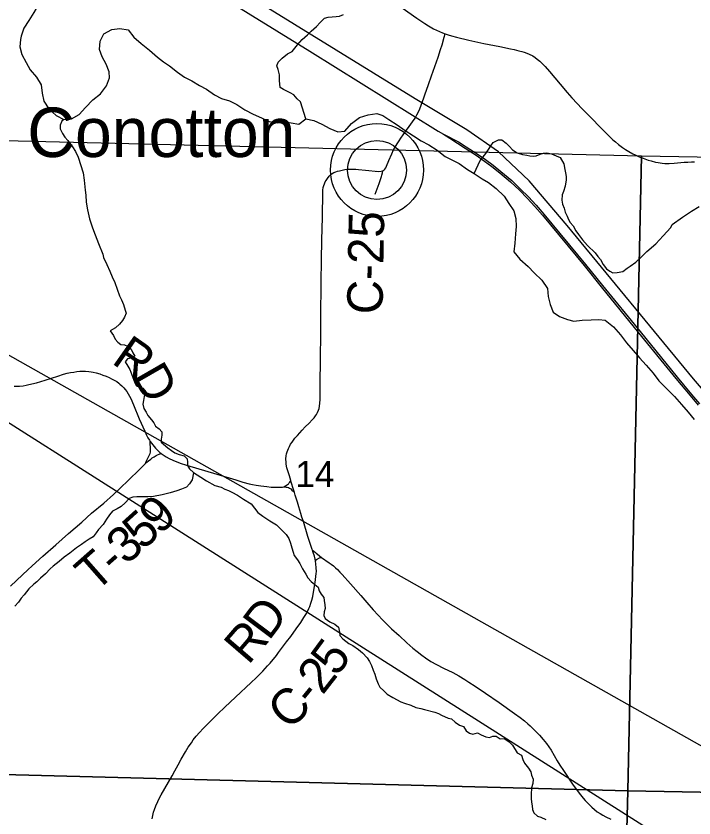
# Model space of a CAD drawing. Extents: x 0 to 34, y 0 to 22.
# Drawn here: x 6.594 to 7.678, y 15.844 to 17.126 of the extents above; entities that cross this region are included whole.
import ezdxf

# ---------------------------------------------------------------- set-up
doc = ezdxf.new("R2010")
doc.units = 0
for name, color, linetype in [('GM_X_Corporation', 7, 'Continuous'), ('GM_X_Corporation_Text', 7, 'Continuous'), ('GM_X_County_Road', 7, 'Continuous'), ('GM_X_County_Road_Text', 7, 'Continuous'), ('GM_X_Interchange_Ramps', 7, 'Continuous'), ('GM_X_Interstate_Route', 7, 'Continuous'), ('GM_X_Major_Lake', 7, 'Continuous'), ('GM_X_Minor_Lake', 7, 'Continuous'), ('GM_X_Section', 7, 'Continuous'), ('GM_X_State_Location', 7, 'Continuous'), ('GM_X_State_Shield', 7, 'Continuous'), ('GM_X_Township_Road_Text', 7, 'Continuous'), ('GM_X_US_Location', 7, 'Continuous'), ('SH_Data', 7, 'Continuous')]:
    doc.layers.add(name, color=color, linetype=linetype)

msp = doc.modelspace()

# ---------------------------------------------------------------- linework, layer by layer
at = {"layer": 'GM_X_Corporation'}
for points in [[(7.2464, 16.9956), (7.2481, 17.0004), (7.2538, 17.0168), (7.2587, 17.0308), (7.2691, 17.0608), (7.2732, 17.073), (7.2756, 17.0805), (7.2789, 17.0927), (7.2803, 17.098)], [(7.0396, 16.3644), (7.038, 16.3695), (7.0345, 16.381), (7.0337, 16.3836), (7.0314, 16.391), (7.0291, 16.3991), (7.0276, 16.4041), (7.0269, 16.4068), (7.0263, 16.4101), (7.0262, 16.4125), (7.0259, 16.4183), (7.0264, 16.4234), (7.027, 16.4266), (7.028, 16.4298), (7.0299, 16.4347), (7.0315, 16.4381), (7.0334, 16.4416), (7.0357, 16.4452), (7.0401, 16.4512), (7.0443, 16.4558), (7.0517, 16.4643), (7.0569, 16.4695), (7.0631, 16.4756), (7.0678, 16.4806), (7.0708, 16.4838), (7.0732, 16.4871), (7.0749, 16.4895), (7.0766, 16.4924), (7.0781, 16.4961), (7.0788, 16.4986), (7.0797, 16.5027), (7.0803, 16.5073), (7.0805, 16.513), (7.0806, 16.5198), (7.0808, 16.5498), (7.081, 16.5657), (7.0811, 16.5722), (7.0812, 16.5824), (7.0813, 16.593), (7.0815, 16.6041), (7.0815, 16.6277), (7.0817, 16.6358), (7.0818, 16.6478), (7.0819, 16.6664), (7.082, 16.6789), (7.0824, 16.6992), (7.0825, 16.7089), (7.0827, 16.7278), (7.0829, 16.7393), (7.0832, 16.7656), (7.0839, 16.7892), (7.0842, 16.8016), (7.0844, 16.8175), (7.0847, 16.8318), (7.0851, 16.8477), (7.0856, 16.8521), (7.0866, 16.8553), (7.0876, 16.8583), (7.0888, 16.8611), (7.0902, 16.8636), (7.0923, 16.8666), (7.0953, 16.8702), (7.0973, 16.8723), (7.0997, 16.8744), (7.1026, 16.8761), (7.1055, 16.8774), (7.1086, 16.8783), (7.1117, 16.8791), (7.1158, 16.8802), (7.1201, 16.8809), (7.1252, 16.8815), (7.1376, 16.8813), (7.1422, 16.8811), (7.1532, 16.8802), (7.1741, 16.878), (7.1782, 16.8781), (7.1806, 16.8788), (7.1816, 16.8794), (7.1828, 16.8803), (7.1841, 16.8817), (7.1856, 16.8839), (7.1869, 16.8866), (7.1904, 16.8953), (7.1951, 16.9062), (7.1981, 16.9125), (7.2004, 16.9167), (7.2038, 16.9223), (7.2068, 16.9268), (7.2097, 16.9313), (7.217, 16.9417), (7.2227, 16.9498), (7.2282, 16.9573), (7.2323, 16.9632), (7.2354, 16.9684), (7.2379, 16.9731), (7.2399, 16.9779), (7.2443, 16.9899), (7.2464, 16.9956)], [(6.5914, 16.5343), (6.5957, 16.5345), (6.6002, 16.5348), (6.6057, 16.5353), (6.6104, 16.5362), (6.6151, 16.5373), (6.6269, 16.5401), (6.641, 16.5441), (6.6614, 16.5508), (6.6701, 16.5535), (6.6763, 16.5551), (6.6817, 16.5564), (6.687, 16.5572), (6.6915, 16.5579), (6.6963, 16.5583), (6.7008, 16.5586), (6.7053, 16.5584), (6.7106, 16.558), (6.7143, 16.5574), (6.718, 16.5569), (6.7228, 16.5557), (6.7282, 16.5541), (6.7334, 16.5522), (6.7386, 16.5503), (6.7432, 16.5483), (6.7471, 16.5463), (6.7515, 16.5442), (6.7556, 16.5418), (6.7586, 16.5396), (6.7606, 16.5379), (6.7638, 16.535), (6.7666, 16.5321), (6.7691, 16.5291), (6.7715, 16.5258), (6.7735, 16.5225), (6.7777, 16.5146), (6.7823, 16.5047), (6.7915, 16.4824), (6.8001, 16.4624), (6.8028, 16.4564), (6.805, 16.4522), (6.8076, 16.4481), (6.809, 16.4461), (6.8109, 16.4435), (6.815, 16.4383), (6.8174, 16.4354), (6.8211, 16.4316), (6.8245, 16.4286), (6.8266, 16.4269), (6.8279, 16.426), (6.8296, 16.4248), (6.8347, 16.4218), (6.8395, 16.4189), (6.8453, 16.4163), (6.8517, 16.4136), (6.8586, 16.4111), (6.8725, 16.4067), (6.9102, 16.3955), (6.9456, 16.3847), (6.9572, 16.3812), (6.9674, 16.3785), (6.9725, 16.3773), (6.9786, 16.3762), (6.986, 16.375), (6.9952, 16.3739), (7.0024, 16.3733), (7.0096, 16.3731), (7.0157, 16.3732), (7.0204, 16.3733), (7.0228, 16.3734)], [(7.0228, 16.3734), (7.0252, 16.375), (7.0269, 16.3762), (7.0285, 16.3774), (7.0299, 16.3786), (7.0306, 16.3794), (7.0319, 16.381), (7.0331, 16.3827), (7.0337, 16.3836)], [(7.0228, 16.3734), (7.0265, 16.3732), (7.0279, 16.373), (7.0301, 16.3723), (7.0318, 16.3715), (7.0337, 16.3702), (7.0356, 16.3685), (7.0375, 16.3665), (7.0396, 16.3644)], [(7.0683, 16.2724), (7.0678, 16.2736), (7.0662, 16.2783), (7.0611, 16.2942), (7.0539, 16.3179), (7.0516, 16.3251), (7.0497, 16.3312), (7.0466, 16.3417), (7.0444, 16.349), (7.0408, 16.3604), (7.0396, 16.3644)], [(6.812, 15.8428), (6.8131, 15.8481), (6.8144, 15.8532), (6.8159, 15.8579), (6.818, 15.8637), (6.8209, 15.8705), (6.8239, 15.8764), (6.8264, 15.881), (6.8438, 15.9117), (6.8484, 15.9197), (6.8537, 15.9288), (6.8586, 15.9381), (6.8652, 15.9497), (6.8697, 15.9572), (6.8747, 15.9643), (6.8777, 15.969), (6.8826, 15.9748), (6.8876, 15.9807), (6.8936, 15.9871), (6.9011, 15.9947), (6.91, 16.0036), (6.9172, 16.0108), (6.9282, 16.0214), (6.9451, 16.037), (6.9701, 16.0608), (6.9781, 16.0682), (6.9888, 16.079), (6.9965, 16.0872), (7.0006, 16.0918), (7.0109, 16.1041), (7.0143, 16.1086), (7.0269, 16.1255), (7.0335, 16.1343), (7.0422, 16.1463), (7.0495, 16.1568), (7.0546, 16.1644), (7.0586, 16.1709), (7.0603, 16.174), (7.0628, 16.179), (7.0642, 16.1824), (7.0659, 16.1874), (7.0674, 16.1926), (7.0687, 16.1983), (7.0713, 16.2118), (7.0727, 16.2208), (7.0745, 16.2352), (7.0747, 16.238), (7.0745, 16.2441), (7.0739, 16.2506), (7.0733, 16.2547), (7.0726, 16.258), (7.0714, 16.2629), (7.0695, 16.2688), (7.0683, 16.2724)], [(7.0683, 16.2724), (7.0699, 16.2711), (7.0711, 16.2701), (7.0724, 16.269), (7.074, 16.2676), (7.0764, 16.2657), (7.0795, 16.2631), (7.083, 16.2606), (7.0953, 16.252), (7.0982, 16.25), (7.1019, 16.2471), (7.1053, 16.2442), (7.1084, 16.2412), (7.1121, 16.2373), (7.1159, 16.2332), (7.129, 16.2184), (7.1457, 16.1996), (7.1554, 16.1886), (7.1656, 16.177), (7.1732, 16.1685), (7.1804, 16.1608), (7.1891, 16.1522), (7.1949, 16.1467), (7.2067, 16.1357), (7.2193, 16.1242), (7.2288, 16.1158), (7.2355, 16.1102), (7.2431, 16.1043), (7.249, 16.1002), (7.2578, 16.0945), (7.2665, 16.0897), (7.278, 16.0839), (7.2926, 16.0768), (7.3023, 16.0715), (7.3118, 16.0657), (7.3186, 16.0614), (7.3283, 16.0551), (7.3451, 16.0435), (7.3668, 16.0285), (7.3915, 16.011), (7.4002, 16.0048), (7.4072, 15.9994), (7.4126, 15.9948), (7.4163, 15.9914), (7.4203, 15.9878), (7.4261, 15.982), (7.4314, 15.9765), (7.4371, 15.9697), (7.4423, 15.9633), (7.4462, 15.9576), (7.4497, 15.9523), (7.4546, 15.9441), (7.4594, 15.9352), (7.4638, 15.9284), (7.4695, 15.9199), (7.4843, 15.8981), (7.4917, 15.8878), (7.4967, 15.8812), (7.501, 15.8759), (7.5044, 15.8721), (7.5101, 15.8664), (7.515, 15.8615), (7.5194, 15.8576), (7.5237, 15.8541), (7.5281, 15.8511), (7.5323, 15.8484), (7.5371, 15.8459), (7.5453, 15.8422)], [(7.0733, 16.2547), (7.0743, 16.2562), (7.075, 16.2572), (7.0759, 16.258), (7.0768, 16.2587), (7.0777, 16.2592), (7.0786, 16.2596), (7.0798, 16.2599), (7.083, 16.2606)]]:
    msp.add_lwpolyline(points, dxfattribs=at)
at = {"layer": 'GM_X_County_Road'}
for points in [[(8.9, 16.3458), (8.8896, 16.3484), (8.8415, 16.3566), (8.7835, 16.3626), (8.6949, 16.3631), (8.0785, 16.3449), (8.0171, 16.3505), (7.9686, 16.3596), (7.9232, 16.3737), (7.8664, 16.3974), (7.8219, 16.4192), (7.7822, 16.4429), (7.7542, 16.4676), (7.7187, 16.4982), (7.6774, 16.5465), (7.4755, 16.7917), (7.4147, 16.863), (7.366, 16.9092), (7.315, 16.9447), (7.2325, 16.9942), (7.0394, 17.1127), (6.8369, 17.2379), (6.5407, 17.4237)], [(6.5677, 17.3781), (6.8144, 17.2247), (7.064, 17.07), (7.2695, 16.9425), (7.2777, 16.9375), (7.3019, 16.9255), (7.3143, 16.9173), (7.3316, 16.9061), (7.3452, 16.8969), (7.357, 16.888), (7.3696, 16.8779), (7.387, 16.8636), (7.4011, 16.8497), (7.4139, 16.8372), (7.4259, 16.8238), (7.4384, 16.8097), (7.5048, 16.7293), (7.5321, 16.6954), (7.592, 16.6219), (7.6516, 16.5487), (7.6743, 16.5214), (7.6872, 16.5062)], [(7.2777, 16.9375), (7.2882, 16.9311), (7.3127, 16.915), (7.3301, 16.9038), (7.3436, 16.8946), (7.3552, 16.8858), (7.3678, 16.8757), (7.3851, 16.8615), (7.3991, 16.8477), (7.4118, 16.8353), (7.4238, 16.8219), (7.4362, 16.8078), (7.5026, 16.7275), (7.5299, 16.6936), (7.5898, 16.6201), (7.6494, 16.5469), (7.6721, 16.5196), (7.6851, 16.5044)]]:
    msp.add_lwpolyline(points, dxfattribs=at)
at = {"layer": 'GM_X_Interchange_Ramps'}
msp.add_lwpolyline([(7.2116, 17.1397), (7.2354, 17.1231), (7.2479, 17.1146), (7.2536, 17.1109), (7.2621, 17.106), (7.2667, 17.1037), (7.2713, 17.1016), (7.2761, 17.0996), (7.2803, 17.098), (7.2853, 17.0963), (7.2904, 17.0947), (7.2987, 17.0926), (7.3186, 17.0879), (7.3422, 17.0825), (7.3679, 17.0775), (7.3849, 17.0741), (7.391, 17.0727), (7.3985, 17.071), (7.4029, 17.0698), (7.4067, 17.0686), (7.4109, 17.067), (7.4147, 17.0654), (7.4204, 17.0625), (7.4246, 17.0599), (7.4274, 17.0577), (7.4318, 17.0545), (7.4362, 17.0501), (7.4403, 17.0457), (7.4473, 17.0377), (7.4643, 17.0174), (7.4756, 17.0039), (7.4829, 16.9958), (7.4994, 16.9782), (7.508, 16.9693), (7.5346, 16.9424), (7.5413, 16.9357), (7.5488, 16.9286), (7.5527, 16.9252), (7.5578, 16.921), (7.5638, 16.9164), (7.5689, 16.913), (7.5742, 16.9097), (7.5804, 16.9062), (7.5843, 16.9043), (7.5905, 16.9015), (7.5968, 16.899), (7.6051, 16.8961), (7.61, 16.8947), (7.6167, 16.893), (7.621, 16.892), (7.6273, 16.8911), (7.6315, 16.8908), (7.6388, 16.8907), (7.6468, 16.8911), (7.6626, 16.8925), (7.6685, 16.8929), (7.6744, 16.8931), (7.6789, 16.8932)], dxfattribs=at)
at = {"layer": 'GM_X_Interstate_Route'}
for points in [[(7.1764, 16.8633), (7.1786, 16.8696), (7.1792, 16.8717), (7.1801, 16.8756), (7.1806, 16.8788)], [(7.1686, 16.8414), (7.1748, 16.8588), (7.1764, 16.8633)], [(6.8009, 16.4101), (6.8018, 16.4125), (6.8035, 16.416), (6.8053, 16.4194), (6.8069, 16.4226), (6.8078, 16.4247), (6.8087, 16.4271), (6.8092, 16.429), (6.8094, 16.4318), (6.8092, 16.4376), (6.809, 16.4411), (6.809, 16.4461)], [(6.5855, 16.2146), (6.5953, 16.224), (6.6045, 16.2327), (6.6134, 16.2411), (6.62, 16.2471), (6.6374, 16.2628), (6.6579, 16.2808), (6.6785, 16.2988), (6.6997, 16.3173), (6.7153, 16.3313), (6.7346, 16.3475), (6.7502, 16.3614), (6.7598, 16.3704), (6.7907, 16.4), (6.8009, 16.4101), (6.8037, 16.4129), (6.806, 16.4149), (6.8097, 16.4178), (6.8122, 16.4198), (6.815, 16.4217), (6.8182, 16.4236), (6.8204, 16.4247), (6.8234, 16.4259), (6.8266, 16.4269)]]:
    msp.add_lwpolyline(points, dxfattribs=at)
at = {"layer": 'GM_X_Minor_Lake'}
for points in [[(7.5942, 16.9027), (7.5725, 15.8874), (6.553, 15.9139), (6.5754, 16.9273)], [(7.5942, 16.9027), (8.606, 16.8847), (8.5869, 15.8686), (7.5725, 15.8874)], [(7.5725, 15.8874), (7.5466, 14.8803), (6.5307, 14.8925), (6.553, 15.9139)], [(7.5725, 15.8874), (8.5869, 15.8686), (8.5685, 14.859), (7.5466, 14.8803)]]:
    msp.add_lwpolyline(points, close=True, dxfattribs=at)
at = {"layer": 'GM_X_State_Location'}
msp.add_line((7.1715, 16.8802), (7.1715, 16.8802), dxfattribs=at)
at = {"layer": 'GM_X_State_Shield'}
for radius in [0.0744, 0.0472]:
    msp.add_circle((7.1715, 16.8802), radius, dxfattribs=at)
at = {"layer": 'GM_X_Township_Road_Text'}
for points in [[(7.0575, 16.9622), (7.049, 16.9893), (7.044, 16.9942), (7.0383, 17.0006), (7.0325, 17.0035), (7.0276, 17.0065), (7.0219, 17.0091), (7.0169, 17.0121), (7.0156, 17.0231), (7.0155, 17.0326), (7.0134, 17.0409), (7.0115, 17.047), (7.0133, 17.0524), (7.02, 17.0589), (7.0286, 17.0659), (7.0357, 17.0698), (7.0443, 17.0802), (7.0521, 17.0887), (7.0604, 17.0965), (7.0663, 17.1023), (7.0749, 17.1096), (7.0805, 17.1162), (7.0876, 17.1228), (7.0933, 17.1244), (7.1001, 17.1249), (7.1065, 17.1257), (7.1118, 17.1262), (7.1182, 17.1286)], [(6.6706, 16.9609), (6.6675, 16.9584), (6.6649, 16.9519), (6.665, 16.9458), (6.6685, 16.9386), (6.6727, 16.9326), (6.677, 16.9273), (6.6847, 16.9172), (6.6897, 16.9096), (6.6937, 16.9005), (6.7016, 16.8755), (6.7033, 16.8638), (6.7046, 16.8531), (6.705, 16.8482), (6.7059, 16.8402), (6.7068, 16.8288), (6.7089, 16.8166), (6.7121, 16.8022), (6.7165, 16.7878), (6.7208, 16.7765), (6.7263, 16.7628), (6.7334, 16.7454), (6.7342, 16.7401), (6.7397, 16.7292), (6.7444, 16.7182), (6.7483, 16.7095), (6.7522, 16.7004), (6.7561, 16.6894), (6.7597, 16.6788), (6.7628, 16.6724), (6.766, 16.6652), (6.7691, 16.6561), (6.7703, 16.6512), (6.7678, 16.6447), (6.7648, 16.6397), (6.7596, 16.6335), (6.7536, 16.6277), (6.745, 16.623), (6.75, 16.6155), (6.7531, 16.6098), (6.757, 16.6049), (6.762, 16.6012), (6.7677, 16.6005), (6.7726, 16.5983), (6.7787, 16.5935), (6.7811, 16.5878), (6.7846, 16.5825), (6.7793, 16.5794), (6.7725, 16.5785), (6.7688, 16.5735), (6.7731, 16.5663), (6.7765, 16.5614), (6.7797, 16.5527), (6.7821, 16.5459), (6.7841, 16.5399), (6.7868, 16.535), (6.7917, 16.5331), (6.7971, 16.5313), (6.8017, 16.5257), (6.7991, 16.518), (6.7981, 16.5119), (6.7974, 16.5058), (6.799, 16.4986), (6.8025, 16.4929), (6.8053, 16.4876), (6.811, 16.4809), (6.8149, 16.476), (6.8176, 16.4707), (6.823, 16.4662), (6.8276, 16.4613), (6.8273, 16.456), (6.8262, 16.4499), (6.8263, 16.445), (6.8371, 16.436), (6.8428, 16.4319), (6.8481, 16.4282), (6.855, 16.4252), (6.8634, 16.4231), (6.868, 16.4182), (6.8684, 16.4132), (6.8685, 16.4075), (6.8716, 16.4026), (6.8781, 16.3963), (6.89, 16.3892), (6.8988, 16.3832), (6.9121, 16.3758), (6.9224, 16.3733), (6.9281, 16.37), (6.9342, 16.3678), (6.9396, 16.3648), (6.9483, 16.36), (6.9579, 16.3541), (6.9701, 16.3463), (6.9809, 16.3323), (6.9889, 16.3268), (7.0004, 16.3193), (7.0107, 16.313), (7.018, 16.3059), (7.0265, 16.2973), (7.0304, 16.2912), (7.0331, 16.2837)], [(7.3267, 16.8748), (7.3366, 16.8955), (7.3414, 16.9012), (7.3455, 16.9066), (7.35, 16.9128), (7.3533, 16.9186), (7.3574, 16.924), (7.366, 16.9287), (7.371, 16.9283), (7.3779, 16.9231), (7.3832, 16.9179), (7.3882, 16.9122), (7.3955, 16.9074), (7.4042, 16.9049), (7.4111, 16.9038), (7.416, 16.9028), (7.4213, 16.9025), (7.4262, 16.9029), (7.4326, 16.9053), (7.4375, 16.9069), (7.4428, 16.9074), (7.4504, 16.906), (7.4577, 16.9026), (7.4645, 16.9001), (7.4703, 16.8899), (7.472, 16.8808), (7.4728, 16.8755), (7.474, 16.8698), (7.4741, 16.8644), (7.4724, 16.8545), (7.4698, 16.8457), (7.4673, 16.8403), (7.467, 16.832), (7.4682, 16.8255), (7.4706, 16.8191), (7.4722, 16.813), (7.4753, 16.8062), (7.4777, 16.8009), (7.4804, 16.796), (7.485, 16.7907), (7.4893, 16.7832), (7.4935, 16.7772), (7.5001, 16.7685), (7.5078, 16.7595), (7.5205, 16.7479), (7.5247, 16.7419), (7.529, 16.737), (7.5332, 16.7291), (7.5386, 16.7223), (7.5436, 16.7186), (7.5486, 16.716), (7.5554, 16.7161), (7.5648, 16.7177), (7.5716, 16.7232), (7.5764, 16.7267), (7.5851, 16.7329), (7.594, 16.741), (7.603, 16.7499), (7.6172, 16.7619), (7.6288, 16.7747), (7.6414, 16.7882), (7.6433, 16.7932), (7.6597, 16.8048), (7.6744, 16.8146), (7.6864, 16.822)], [(6.8782, 16.3962), (6.876, 16.3848), (6.872, 16.3783), (6.8671, 16.3732), (6.8588, 16.3697), (6.8517, 16.3673), (6.8407, 16.3641), (6.8283, 16.3609), (6.8143, 16.358), (6.8049, 16.3575), (6.7954, 16.3577), (6.7878, 16.3576), (6.781, 16.3571), (6.7754, 16.3547), (6.7687, 16.3481), (6.7627, 16.342), (6.7559, 16.3384), (6.7484, 16.3349), (6.7436, 16.3287), (6.7391, 16.3218), (6.7336, 16.3134), (6.7265, 16.3056), (6.7228, 16.2999), (6.7176, 16.2937), (6.7112, 16.2898), (6.7052, 16.2855), (6.6992, 16.2816), (6.691, 16.2758), (6.6805, 16.2676), (6.6715, 16.261), (6.6633, 16.2544), (6.6539, 16.2467), (6.649, 16.2424), (6.6416, 16.2343), (6.6337, 16.2273), (6.6278, 16.2219), (6.6229, 16.218), (6.6151, 16.2103), (6.6072, 16.201), (6.6028, 16.1953), (6.5983, 16.1891), (6.5924, 16.1829)], [(7.0331, 16.2837), (7.0355, 16.2761), (7.0375, 16.2689), (7.0391, 16.264), (7.0445, 16.2568), (7.048, 16.2508), (7.0526, 16.2425), (7.0577, 16.2338), (7.0612, 16.2281), (7.0662, 16.2221), (7.0719, 16.2173), (7.0777, 16.2132), (7.0793, 16.2071), (7.0824, 16.2018), (7.0863, 16.1965), (7.0871, 16.1916), (7.0879, 16.1848), (7.0884, 16.1791), (7.087, 16.1737), (7.0863, 16.168), (7.0886, 16.1631), (7.0959, 16.1575), (7.1039, 16.1542), (7.1097, 16.1493), (7.1117, 16.141), (7.1121, 16.1357), (7.1167, 16.1304), (7.1267, 16.1233), (7.1328, 16.12), (7.142, 16.1137), (7.1485, 16.1084), (7.1558, 16.1002), (7.1593, 16.0945), (7.1628, 16.0881), (7.1656, 16.0805), (7.1679, 16.0741), (7.1703, 16.0665), (7.1735, 16.0586), (7.1762, 16.0533), (7.1827, 16.0473), (7.1877, 16.042), (7.1969, 16.0365), (7.2098, 16.0298), (7.2155, 16.0276), (7.2258, 16.0243), (7.2338, 16.0207), (7.2414, 16.0193), (7.2475, 16.0174), (7.2638, 16.0131), (7.2696, 16.0109), (7.2749, 16.0083), (7.2852, 16.0039), (7.2905, 16.0025), (7.2966, 15.9973), (7.3035, 15.9924), (7.3096, 15.9902), (7.3139, 15.9834), (7.3196, 15.9797), (7.3249, 15.9779), (7.3321, 15.9803), (7.3378, 15.977), (7.3454, 15.974), (7.3515, 15.9726), (7.3568, 15.975), (7.3621, 15.9747), (7.3686, 15.9706), (7.3746, 15.971), (7.383, 15.9658), (7.388, 15.9606), (7.3958, 15.9485), (7.4023, 15.9444), (7.4047, 15.9376), (7.4074, 15.9316), (7.4136, 15.9237), (7.4174, 15.9177), (7.4183, 15.9123), (7.421, 15.9063), (7.4204, 15.8994), (7.4186, 15.8925), (7.418, 15.8815), (7.4181, 15.875), (7.4185, 15.8693), (7.4194, 15.8636), (7.4202, 15.8576), (7.4222, 15.8523), (7.4279, 15.847), (7.4336, 15.8456), (7.4413, 15.8415)]]:
    msp.add_lwpolyline(points, dxfattribs=at)
at = {"layer": 'GM_X_US_Location'}
for points in [[(6.5872, 17.2281), (6.5969, 17.2157), (6.6088, 17.2037), (6.6207, 17.1947), (6.6273, 17.1831), (6.6305, 17.1698), (6.6314, 17.1577), (6.6304, 17.1451), (6.623, 17.1318), (6.6148, 17.1192), (6.6069, 17.1069), (6.6029, 17.094)], [(6.6029, 17.094), (6.6015, 17.089), (6.6005, 17.0769), (6.6036, 17.0648), (6.6106, 17.0519), (6.6172, 17.0403), (6.6273, 17.0286), (6.6346, 17.0166), (6.6363, 17.0029), (6.6391, 16.9904), (6.6469, 16.978), (6.6584, 16.9672), (6.6706, 16.9609), (6.6831, 16.9622), (6.6952, 16.9687), (6.7053, 16.9803), (6.7173, 16.9925), (6.7297, 17.0022), (6.7391, 17.0148), (6.7438, 17.0278), (6.7433, 17.0372), (6.7386, 17.0493), (6.732, 17.0614), (6.7277, 17.0731), (6.7287, 17.0864), (6.735, 17.0979), (6.7475, 17.1048), (6.7604, 17.1065), (6.7737, 17.1044), (6.7829, 17.0924), (6.7944, 17.0826), (6.8079, 17.0718), (6.8205, 17.0606), (6.8301, 17.0531), (6.8397, 17.0468), (6.8527, 17.0367), (6.8638, 17.0285), (6.8757, 17.0229), (6.8875, 17.0155), (6.899, 17.0096), (6.9116, 17.0006), (6.9231, 16.9943), (6.9357, 16.991), (6.9475, 16.9847), (6.9602, 16.9765), (6.9735, 16.9695), (6.9869, 16.9636), (6.9991, 16.9577), (7.0117, 16.9555), (7.0249, 16.9572), (7.0345, 16.9558), (7.0463, 16.9533), (7.0575, 16.9622), (7.0705, 16.9593), (7.0835, 16.9534), (7.0961, 16.9467), (7.1087, 16.9412), (7.1201, 16.9421), (7.1305, 16.9547), (7.1437, 16.964), (7.1573, 16.9683), (7.1714, 16.9708), (7.1809, 16.9675), (7.1905, 16.9611), (7.2039, 16.9522), (7.2165, 16.9433), (7.2299, 16.9347), (7.2421, 16.9269), (7.2544, 16.9202), (7.2678, 16.912), (7.2804, 16.9019), (7.2934, 16.8956), (7.303, 16.8904), (7.3164, 16.8811), (7.3267, 16.8748), (7.3397, 16.8662), (7.3497, 16.8603), (7.3619, 16.8506), (7.375, 16.8382), (7.3824, 16.8269), (7.3901, 16.8149), (7.3937, 16.8028), (7.3942, 16.7899), (7.3928, 16.7781), (7.3919, 16.7633), (7.3905, 16.7496), (7.3998, 16.7376), (7.4132, 16.726), (7.4228, 16.7159), (7.4351, 16.7039), (7.444, 16.6908), (7.4453, 16.6779), (7.4481, 16.6654), (7.4532, 16.6529), (7.4632, 16.6462), (7.4762, 16.6411), (7.4861, 16.6385), (7.4993, 16.6402), (7.5138, 16.6408), (7.5263, 16.6413), (7.5365, 16.6403)], [(7.5365, 16.6403), (7.5496, 16.6295), (7.5608, 16.6167), (7.5704, 16.6039), (7.5812, 16.5915), (7.5912, 16.5799), (7.6016, 16.5683), (7.6128, 16.5555), (7.622, 16.5431), (7.6347, 16.5304), (7.647, 16.518), (7.6582, 16.5053), (7.669, 16.4929), (7.6786, 16.4812)]]:
    msp.add_lwpolyline(points, dxfattribs=at)
at = {"layer": 'SH_Data'}
msp.add_lwpolyline([(9.2998, 15.0505), (5.0551, 17.4465), (9.2998, 14.751)], close=True, dxfattribs=at)

# ---------------------------------------------------------------- texts
at = {"layer": 'GM_X_Corporation_Text'}
msp.add_text('Conotton', height=0.07898, rotation=0, dxfattribs=at).set_placement((6.6124, 16.901))
at = {"layer": 'GM_X_County_Road_Text'}
msp.add_text('14', height=0.04186, rotation=0, dxfattribs=at).set_placement((7.0411, 16.3731))
at = {"layer": 'GM_X_Major_Lake'}
for s, height, rotation, p in [('C-25', 0.05682, 88.9662, (7.1803, 16.6491)), ('R', 0.0568, 325.0953, (6.7455, 16.5722)), ('D', 0.0568, 299.931, (6.7794, 16.5503)), ('D', 0.0568, 53.1804, (6.9987, 16.1261)), ('R', 0.0568, 49.3233, (6.9657, 16.0875)), ('5', 0.0568, 53.6791, (7.1072, 16.0686)), ('2', 0.0568, 51.9858, (7.0845, 16.0395)), ('C', 0.0568, 44.448, (7.031, 15.9827)), ('-', 0.0568, 50.7452, (7.0689, 16.0204))]:
    msp.add_text(s, height=height, rotation=rotation, dxfattribs=at).set_placement(p)
at = {"layer": 'GM_X_Section'}
for s, rotation, p in [('9', 43.5523, (6.8242, 16.2955)), ('5', 42.0841, (6.797, 16.271)), ('3', 41.6112, (6.7705, 16.2474)), ('T', 41.3641, (6.7209, 16.2037)), ('-', 41.4024, (6.7528, 16.2318))]:
    msp.add_text(s, height=0.0568, rotation=rotation, dxfattribs=at).set_placement(p)

doc.saveas('drawing.dxf')
